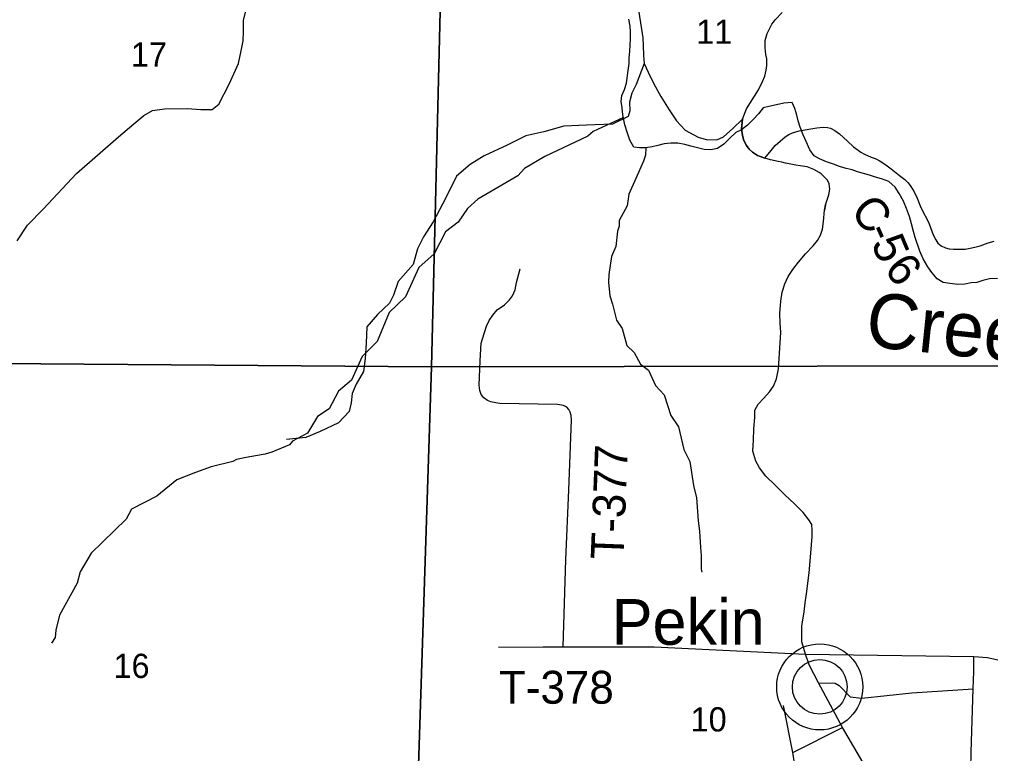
# Model space of a CAD drawing. Extents: x 2.1 to 8.9, y 14.1 to 20.9.
# Drawn here: x 3.78 to 5.459, y 16.441 to 17.71 of the extents above; entities that cross this region are included whole.
import ezdxf

# ---------------------------------------------------------------- set-up
doc = ezdxf.new("R2010")
doc.units = 0
for name, color, linetype in [('GM_X_City_Street', 7, 'Continuous'), ('GM_X_County_Road_Text', 7, 'Continuous'), ('GM_X_Interchange_Ramps', 7, 'Continuous'), ('GM_X_Major_River', 7, 'Continuous'), ('GM_X_Minor_River', 7, 'Continuous'), ('GM_X_Minor_River_Text', 7, 'Continuous'), ('GM_X_Rail_Line_Text', 7, 'Continuous'), ('GM_X_State_Route', 7, 'Continuous'), ('GM_X_State_Shield', 7, 'Continuous'), ('GM_X_Township_Text', 7, 'Continuous'), ('PV_P_Text', 7, 'Continuous'), ('SH_Data', 7, 'Continuous'), ('TX_P_Misc', 7, 'Continuous')]:
    doc.layers.add(name, color=color, linetype=linetype)

msp = doc.modelspace()

# ---------------------------------------------------------------- linework, layer by layer
at = {"layer": 'GM_X_City_Street'}
for p, q in [((4.1678, 17.7086), (4.176, 17.7412)), ((4.1675, 17.6895), (4.1678, 17.7086)), ((4.1668, 17.673), (4.1675, 17.6895)), ((4.1636, 17.6561), (4.1668, 17.673)), ((4.159, 17.6343), (4.1636, 17.6561)), ((4.1427, 17.5984), (4.159, 17.6343)), ((4.8603, 17.634), (4.8464, 17.598)), ((4.1252, 17.5639), (4.1427, 17.5984)), ((4.8464, 17.598), (4.8387, 17.5827)), ((4.8387, 17.5827), (4.8348, 17.5674)), ((4.1137, 17.5544), (4.1252, 17.5639)), ((4.8348, 17.5674), (4.8351, 17.5522)), ((3.9781, 17.5298), (3.9953, 17.544)), ((3.9953, 17.544), (4.0106, 17.5526)), ((4.0106, 17.5526), (4.0313, 17.5558)), ((4.0313, 17.5558), (4.0706, 17.5564)), ((4.0706, 17.5564), (4.0942, 17.5547)), ((4.0942, 17.5547), (4.099, 17.5547)), ((4.099, 17.5547), (4.1137, 17.5544)), ((4.8323, 17.5423), (4.8056, 17.5293)), ((4.8351, 17.5522), (4.8323, 17.5423)), ((3.9517, 17.5074), (3.9781, 17.5298)), ((4.7213, 17.5255), (4.6867, 17.5158)), ((4.7603, 17.5273), (4.7213, 17.5255)), ((4.8056, 17.5293), (4.7603, 17.5273)), ((3.8789, 17.4441), (3.9517, 17.5074)), ((4.6558, 17.5088), (4.6236, 17.493)), ((4.6867, 17.5158), (4.6558, 17.5088)), ((4.6236, 17.493), (4.5834, 17.4744)), ((4.5834, 17.4744), (4.5595, 17.4596)), ((4.5595, 17.4596), (4.536, 17.4394)), ((3.8222, 17.383), (3.8789, 17.4441)), ((4.536, 17.4394), (4.5166, 17.4007)), ((4.5166, 17.4007), (4.4957, 17.3604)), ((3.7944, 17.3548), (3.8222, 17.383)), ((4.4957, 17.3604), (4.4788, 17.3347)), ((3.7763, 17.3273), (3.7944, 17.3548)), ((4.4788, 17.3347), (4.4682, 17.3136)), ((4.4682, 17.3136), (4.4611, 17.2865)), ((4.4611, 17.2865), (4.4351, 17.2575)), ((4.6397, 17.2557), (4.6457, 17.279)), ((4.4351, 17.2575), (4.4268, 17.2338)), ((4.6373, 17.243), (4.6397, 17.2557)), ((4.6324, 17.2326), (4.6373, 17.243)), ((4.4268, 17.2338), (4.4199, 17.2197)), ((4.6186, 17.217), (4.6272, 17.2254)), ((4.6272, 17.2254), (4.6324, 17.2326)), ((4.4199, 17.2197), (4.3994, 17.2003)), ((4.5987, 17.1993), (4.6062, 17.2083)), ((4.6062, 17.2083), (4.6186, 17.217)), ((4.3994, 17.2003), (4.3809, 17.1791)), ((4.5877, 17.1799), (4.5923, 17.1899)), ((4.5923, 17.1899), (4.5987, 17.1993)), ((4.3809, 17.1791), (4.3795, 17.1506)), ((4.5805, 17.1584), (4.5877, 17.1799)), ((4.5787, 17.1504), (4.5805, 17.1584)), ((4.3795, 17.1506), (4.3777, 17.1239)), ((4.5765, 17.1201), (4.5787, 17.1504)), ((4.3777, 17.1239), (4.375, 17.1015)), ((4.5751, 17.0782), (4.5765, 17.1201)), ((4.375, 17.1015), (4.3625, 17.08)), ((4.3625, 17.08), (4.3556, 17.0639)), ((4.5761, 17.0691), (4.5751, 17.0782)), ((4.3556, 17.0639), (4.354, 17.0475)), ((4.5785, 17.0619), (4.5761, 17.0691)), ((4.5829, 17.0561), (4.5785, 17.0619)), ((4.5893, 17.0513), (4.5829, 17.0561)), ((4.354, 17.0475), (4.3501, 17.0323)), ((4.5949, 17.0491), (4.5893, 17.0513)), ((4.6038, 17.0473), (4.5949, 17.0491)), ((4.6106, 17.0463), (4.6038, 17.0473)), ((4.7105, 17.0445), (4.6106, 17.0463)), ((4.7205, 17.0429), (4.7105, 17.0445)), ((4.7263, 17.0399), (4.7205, 17.0429)), ((4.7301, 17.036), (4.7263, 17.0399)), ((4.3501, 17.0323), (4.3319, 17.0129)), ((4.7325, 17.0316), (4.7301, 17.036)), ((4.7339, 17.0258), (4.7325, 17.0316)), ((4.7345, 17.0182), (4.7339, 17.0258)), ((4.3319, 17.0129), (4.3, 16.9979)), ((4.7299, 16.8968), (4.7345, 17.0182)), ((4.2752, 16.9876), (4.242, 16.984)), ((4.3, 16.9979), (4.2752, 16.9876)), ((4.7249, 16.7769), (4.7299, 16.8968)), ((4.7199, 16.6259), (4.7249, 16.7769)), ((4.6084, 16.625), (4.6858, 16.6257)), ((4.6858, 16.6257), (4.7018, 16.6259)), ((4.7018, 16.6259), (4.7199, 16.6259)), ((4.7199, 16.6259), (4.7998, 16.6259)), ((4.7998, 16.6259), (4.8777, 16.626)), ((4.8777, 16.626), (5.1389, 16.613)), ((5.1389, 16.613), (5.4299, 16.6088)), ((5.4299, 16.6088), (5.4537, 16.6073)), ((5.4299, 16.5831), (5.4299, 16.6088)), ((5.4537, 16.6073), (5.4922, 16.5985)), ((5.429, 16.5529), (5.4299, 16.5831)), ((5.1612, 16.5634), (5.1902, 16.5627)), ((5.1902, 16.5627), (5.1974, 16.5586)), ((5.1974, 16.5586), (5.216, 16.5394)), ((5.3225, 16.5464), (5.429, 16.5529)), ((5.4251, 16.4434), (5.429, 16.5529)), ((5.216, 16.5394), (5.2363, 16.537)), ((5.2363, 16.537), (5.3225, 16.5464)), ((5.1173, 16.4432), (5.1012, 16.5243)), ((5.1173, 16.4432), (5.2031, 16.4864)), ((5.1293, 16.3639), (5.1173, 16.4432)), ((5.4248, 16.415), (5.4251, 16.4434))]:
    msp.add_line(p, q, dxfattribs=at)
at = {"layer": 'GM_X_Interchange_Ramps'}
for p, q in [((4.5166, 18.1148), (4.4928, 17.1099)), ((4.4928, 17.1099), (4.5166, 18.1148)), ((4.4928, 17.1099), (3.4934, 17.1171)), ((3.4934, 17.1171), (4.4928, 17.1099)), ((4.4928, 17.1099), (4.4591, 16.088)), ((4.4591, 16.088), (4.4928, 17.1099)), ((5.492, 17.1117), (4.4928, 17.1099)), ((4.4928, 17.1099), (5.492, 17.1117))]:
    msp.add_line(p, q, dxfattribs=at)
at = {"layer": 'GM_X_Rail_Line_Text'}
for p, q in [((5.0839, 17.7058), (5.0867, 17.7098)), ((5.0867, 17.7098), (5.0989, 17.7224)), ((5.0728, 17.686), (5.0766, 17.6941)), ((5.0766, 17.6941), (5.081, 17.7018)), ((5.081, 17.7018), (5.0839, 17.7058)), ((5.0695, 17.6737), (5.0728, 17.686)), ((5.0695, 17.6611), (5.0695, 17.6737)), ((5.0705, 17.6494), (5.0695, 17.6611)), ((5.0719, 17.6422), (5.0705, 17.6494)), ((5.0722, 17.6308), (5.0719, 17.6422)), ((5.0713, 17.6223), (5.0722, 17.6308)), ((5.0649, 17.6028), (5.0685, 17.6121)), ((5.0685, 17.6121), (5.0713, 17.6223)), ((5.0577, 17.5884), (5.0649, 17.6028)), ((5.0373, 17.556), (5.0507, 17.5778)), ((5.0507, 17.5778), (5.0577, 17.5884)), ((5.0299, 17.5378), (5.0373, 17.556)), ((5.0283, 17.5209), (5.0299, 17.5378)), ((5.0301, 17.5094), (5.0283, 17.5209)), ((5.0322, 17.5009), (5.0301, 17.5094)), ((5.0369, 17.4925), (5.0322, 17.5009)), ((5.0418, 17.4862), (5.0369, 17.4925)), ((5.0473, 17.4808), (5.0418, 17.4862)), ((5.0559, 17.4751), (5.0473, 17.4808)), ((5.0686, 17.4706), (5.0559, 17.4751)), ((5.0783, 17.4676), (5.0686, 17.4706)), ((5.0918, 17.4648), (5.0783, 17.4676)), ((5.0983, 17.4634), (5.0918, 17.4648)), ((5.1047, 17.4616), (5.0983, 17.4634)), ((5.1076, 17.4611), (5.1047, 17.4616)), ((5.1222, 17.4586), (5.1076, 17.4611)), ((5.1296, 17.4574), (5.1222, 17.4586)), ((5.1418, 17.4552), (5.1296, 17.4574)), ((5.1535, 17.4507), (5.1418, 17.4552)), ((5.1624, 17.4455), (5.1535, 17.4507)), ((5.1662, 17.4432), (5.1624, 17.4455)), ((5.1702, 17.4396), (5.1662, 17.4432)), ((5.1769, 17.4324), (5.1702, 17.4396)), ((5.1799, 17.4258), (5.1769, 17.4324)), ((5.1812, 17.4169), (5.1799, 17.4258)), ((5.1737, 17.3895), (5.1794, 17.407)), ((5.1794, 17.407), (5.1812, 17.4169)), ((5.1721, 17.3806), (5.1737, 17.3895)), ((5.1702, 17.3611), (5.1721, 17.3806)), ((5.1682, 17.3477), (5.1702, 17.3611)), ((5.1649, 17.3375), (5.1682, 17.3477)), ((5.1521, 17.3188), (5.1597, 17.3283)), ((5.1597, 17.3283), (5.1649, 17.3375)), ((5.1389, 17.3052), (5.1521, 17.3188)), ((5.117, 17.2778), (5.1267, 17.2904)), ((5.1267, 17.2904), (5.1389, 17.3052)), ((5.1093, 17.2659), (5.117, 17.2778)), ((5.103, 17.2531), (5.1093, 17.2659)), ((5.0962, 17.2232), (5.0984, 17.239)), ((5.0984, 17.239), (5.103, 17.2531)), ((5.0945, 17.2019), (5.0962, 17.2232)), ((5.095, 17.1857), (5.0945, 17.2019)), ((5.0962, 17.1691), (5.095, 17.1857)), ((5.0954, 17.1513), (5.0962, 17.1691)), ((5.0923, 17.106), (5.0954, 17.1513)), ((5.0887, 17.0888), (5.0923, 17.106)), ((5.0836, 17.0762), (5.0887, 17.0888)), ((5.0768, 17.0667), (5.0836, 17.0762)), ((5.0569, 17.0452), (5.0671, 17.0558)), ((5.0671, 17.0558), (5.0768, 17.0667)), ((5.0516, 17.0347), (5.0569, 17.0452)), ((5.0498, 17.0028), (5.0514, 17.0224)), ((5.0514, 17.0224), (5.0516, 17.0347)), ((5.049, 16.9831), (5.0498, 17.0028)), ((5.0479, 16.9641), (5.049, 16.9831)), ((5.0534, 16.9467), (5.0479, 16.9641)), ((5.0595, 16.9353), (5.0534, 16.9467)), ((5.0704, 16.9205), (5.0595, 16.9353)), ((5.0863, 16.9054), (5.0704, 16.9205)), ((5.1025, 16.8889), (5.0863, 16.9054)), ((5.1206, 16.8725), (5.1025, 16.8889)), ((5.135, 16.8581), (5.1206, 16.8725)), ((5.145, 16.8452), (5.135, 16.8581)), ((5.1498, 16.8371), (5.145, 16.8452)), ((5.1507, 16.8268), (5.1498, 16.8371)), ((5.1507, 16.8166), (5.1507, 16.8268)), ((5.1483, 16.7874), (5.1507, 16.8166)), ((5.1452, 16.7535), (5.1483, 16.7874)), ((5.1406, 16.7175), (5.1452, 16.7535)), ((5.1367, 16.6861), (5.1386, 16.7018)), ((5.1386, 16.7018), (5.1406, 16.7175)), ((5.1324, 16.6612), (5.1367, 16.6861)), ((5.1326, 16.6346), (5.1324, 16.6612)), ((5.1389, 16.613), (5.1326, 16.6346)), ((5.1454, 16.5944), (5.1389, 16.613)), ((5.1612, 16.5634), (5.1454, 16.5944)), ((5.2031, 16.4864), (5.1612, 16.5634)), ((5.2634, 16.3835), (5.2031, 16.4864))]:
    msp.add_line(p, q, dxfattribs=at)
at = {"layer": 'GM_X_State_Route'}
for radius in [0.0744, 0.0472]:
    msp.add_circle((5.1636, 16.5565), radius, dxfattribs=at)
at = {"layer": 'GM_X_State_Shield'}
for p, q in [((4.8512, 17.7226), (4.8578, 17.6782)), ((4.8578, 17.6782), (4.8582, 17.665)), ((4.8582, 17.665), (4.8589, 17.6477)), ((4.8589, 17.6477), (4.8603, 17.634)), ((4.8603, 17.634), (4.8668, 17.619)), ((4.8668, 17.619), (4.8766, 17.599)), ((4.8766, 17.599), (4.8891, 17.577)), ((4.8891, 17.577), (4.9036, 17.5542)), ((4.9036, 17.5542), (4.9163, 17.535)), ((4.9163, 17.535), (4.9313, 17.5189)), ((5.0135, 17.5215), (5.0299, 17.5378)), ((5.0299, 17.5378), (5.0283, 17.5209)), ((5.1587, 17.5231), (5.1696, 17.5238)), ((5.1696, 17.5238), (5.177, 17.5233)), ((4.9313, 17.5189), (4.9536, 17.5067)), ((4.9536, 17.5067), (4.9673, 17.503)), ((4.9857, 17.5023), (4.9971, 17.5075)), ((4.9971, 17.5075), (5.0135, 17.5215)), ((5.0283, 17.5209), (5.0301, 17.5094)), ((5.0301, 17.5094), (5.0322, 17.5009)), ((5.0865, 17.4923), (5.1041, 17.5075)), ((5.1041, 17.5075), (5.1103, 17.5112)), ((5.1103, 17.5112), (5.1167, 17.5141)), ((5.1167, 17.5141), (5.1225, 17.5161)), ((5.1225, 17.5161), (5.1282, 17.5178)), ((5.1282, 17.5178), (5.1587, 17.5231)), ((5.177, 17.5233), (5.182, 17.5223)), ((5.182, 17.5223), (5.1897, 17.5185)), ((5.1897, 17.5185), (5.1979, 17.5124)), ((5.1979, 17.5124), (5.2118, 17.4998)), ((4.9673, 17.503), (4.9857, 17.5023)), ((5.0322, 17.5009), (5.0369, 17.4925)), ((5.0369, 17.4925), (5.0418, 17.4862)), ((5.0794, 17.4839), (5.0865, 17.4923)), ((5.2118, 17.4998), (5.2222, 17.4903)), ((5.2222, 17.4903), (5.2299, 17.4843)), ((5.0418, 17.4862), (5.0473, 17.4808)), ((5.0473, 17.4808), (5.0559, 17.4751)), ((5.0559, 17.4751), (5.0686, 17.4706)), ((5.0686, 17.4706), (5.0794, 17.4839)), ((5.2299, 17.4843), (5.2346, 17.4811)), ((5.2346, 17.4811), (5.2411, 17.4774)), ((5.2411, 17.4774), (5.2527, 17.4719)), ((5.2527, 17.4719), (5.2592, 17.4697)), ((5.2592, 17.4697), (5.2663, 17.4665)), ((5.2663, 17.4665), (5.2777, 17.4591)), ((5.2777, 17.4591), (5.2871, 17.4519)), ((5.2871, 17.4519), (5.3015, 17.4404)), ((5.3015, 17.4404), (5.3105, 17.4337)), ((5.3105, 17.4337), (5.3164, 17.4276)), ((5.3164, 17.4276), (5.3209, 17.4216)), ((5.3209, 17.4216), (5.3266, 17.4121)), ((5.3266, 17.4121), (5.3318, 17.4013)), ((5.3318, 17.4013), (5.3373, 17.3878)), ((5.3373, 17.3878), (5.3428, 17.376)), ((5.3428, 17.376), (5.3484, 17.3665)), ((5.3484, 17.3665), (5.3526, 17.3568)), ((5.3526, 17.3568), (5.3594, 17.3382)), ((5.3594, 17.3382), (5.3641, 17.3291)), ((5.3641, 17.3291), (5.3676, 17.3233)), ((5.3676, 17.3233), (5.3735, 17.3189)), ((5.4407, 17.3191), (5.4548, 17.3238)), ((5.4548, 17.3238), (5.465, 17.3268)), ((5.3735, 17.3189), (5.3809, 17.3154)), ((5.3809, 17.3154), (5.3874, 17.3137)), ((5.3874, 17.3137), (5.3949, 17.313)), ((5.3949, 17.313), (5.406, 17.3129)), ((5.406, 17.3129), (5.4152, 17.3134)), ((5.4152, 17.3134), (5.4234, 17.3149)), ((5.4234, 17.3149), (5.4315, 17.3166)), ((5.4315, 17.3166), (5.4407, 17.3191))]:
    msp.add_line(p, q, dxfattribs=at)
at = {"layer": 'GM_X_Township_Text'}
msp.add_line((5.1636, 16.5565), (5.1636, 16.5565), dxfattribs=at)
at = {"layer": 'SH_Data'}
msp.add_line((5.1737, 17.3895), (5.1721, 17.3806), dxfattribs=at)
msp.add_lwpolyline([(5.1737, 17.3895), (5.1794, 17.407), (5.1794, 17.407), (5.1812, 17.4169), (5.1799, 17.4258), (5.1769, 17.4324), (5.1702, 17.4396), (5.1662, 17.4432), (5.1624, 17.4455), (5.1535, 17.4507), (5.1418, 17.4552), (5.1296, 17.4574), (5.1222, 17.4586), (5.1076, 17.4611), (5.1047, 17.4616), (5.0983, 17.4634), (5.0918, 17.4648), (5.0783, 17.4676)], dxfattribs=at)
at = {"layer": 'TX_P_Misc'}
for p, q in [((4.8359, 17.6988), (4.8336, 17.7106)), ((4.8365, 17.689), (4.8359, 17.6988)), ((4.8357, 17.6661), (4.8366, 17.6756)), ((4.8366, 17.6756), (4.8365, 17.689)), ((4.8353, 17.6547), (4.8357, 17.6661)), ((4.834, 17.6341), (4.8345, 17.644)), ((4.8345, 17.644), (4.8353, 17.6547)), ((4.8325, 17.6222), (4.834, 17.6341)), ((4.8298, 17.6), (4.8325, 17.6222)), ((4.8263, 17.5889), (4.8298, 17.6)), ((4.8205, 17.5685), (4.8213, 17.5788)), ((4.8213, 17.5788), (4.8263, 17.5889)), ((4.8223, 17.5572), (4.8205, 17.5685)), ((4.8235, 17.5454), (4.8223, 17.5572)), ((5.0657, 17.5572), (5.0576, 17.547)), ((5.0755, 17.5598), (5.0657, 17.5572)), ((5.0891, 17.5629), (5.0755, 17.5598)), ((5.1015, 17.5656), (5.0891, 17.5629)), ((5.116, 17.5668), (5.1015, 17.5656)), ((5.1205, 17.5563), (5.116, 17.5668)), ((4.8244, 17.5409), (4.7719, 17.5168)), ((4.827, 17.528), (4.8235, 17.5454)), ((5.0576, 17.547), (5.0484, 17.5372)), ((5.1239, 17.5446), (5.1205, 17.5563)), ((5.1261, 17.5347), (5.1239, 17.5446)), ((4.8308, 17.5156), (4.827, 17.528)), ((5.0388, 17.5274), (5.0284, 17.5195)), ((5.0484, 17.5372), (5.0388, 17.5274)), ((5.1298, 17.5242), (5.1261, 17.5347)), ((5.1348, 17.511), (5.1298, 17.5242)), ((4.7629, 17.5087), (4.6883, 17.4736)), ((4.7719, 17.5168), (4.7629, 17.5087)), ((4.8355, 17.5016), (4.8308, 17.5156)), ((5.0187, 17.515), (5.0084, 17.5048)), ((5.0284, 17.5195), (5.0187, 17.515)), ((5.1401, 17.499), (5.1348, 17.511)), ((4.8423, 17.4893), (4.8355, 17.5016)), ((4.8742, 17.4903), (4.8632, 17.4884)), ((4.884, 17.4921), (4.8742, 17.4903)), ((4.895, 17.4951), (4.884, 17.4921)), ((4.9063, 17.4962), (4.895, 17.4951)), ((4.9185, 17.4962), (4.9063, 17.4962)), ((4.9304, 17.4939), (4.9185, 17.4962)), ((4.9407, 17.4912), (4.9304, 17.4939)), ((4.9526, 17.4885), (4.9407, 17.4912)), ((4.9976, 17.4949), (4.9868, 17.4873)), ((5.0084, 17.5048), (4.9976, 17.4949)), ((5.1462, 17.4851), (5.1401, 17.499)), ((4.6883, 17.4736), (4.6535, 17.4524)), ((4.8522, 17.4884), (4.8423, 17.4893)), ((4.8632, 17.4884), (4.8522, 17.4884)), ((4.8622, 17.4757), (4.8589, 17.4654)), ((4.8633, 17.4884), (4.8622, 17.4757)), ((4.9637, 17.4855), (4.9526, 17.4885)), ((4.9755, 17.4847), (4.9637, 17.4855)), ((4.9868, 17.4873), (4.9755, 17.4847)), ((5.1538, 17.4747), (5.1462, 17.4851)), ((5.1634, 17.4693), (5.1538, 17.4747)), ((4.8589, 17.4654), (4.8458, 17.4355)), ((5.1754, 17.4639), (5.1634, 17.4693)), ((5.1873, 17.4601), (5.1754, 17.4639)), ((5.198, 17.4563), (5.1873, 17.4601)), ((4.642, 17.4397), (4.5728, 17.3993)), ((4.6535, 17.4524), (4.642, 17.4397)), ((5.2092, 17.4528), (5.198, 17.4563)), ((5.2195, 17.4501), (5.2092, 17.4528)), ((5.2291, 17.447), (5.2195, 17.4501)), ((5.2391, 17.4438), (5.2291, 17.447)), ((5.2498, 17.4408), (5.2391, 17.4438)), ((5.2598, 17.4376), (5.2498, 17.4408)), ((4.8458, 17.4355), (4.8338, 17.4082)), ((5.2702, 17.4349), (5.2598, 17.4376)), ((5.2829, 17.43), (5.2702, 17.4349)), ((5.2942, 17.4201), (5.2829, 17.43)), ((4.8338, 17.4082), (4.8308, 17.388)), ((5.301, 17.4092), (5.2942, 17.4201)), ((5.3082, 17.3961), (5.301, 17.4092)), ((4.5728, 17.3993), (4.5549, 17.3834)), ((5.3136, 17.3833), (5.3082, 17.3961)), ((4.5549, 17.3834), (4.5387, 17.36)), ((4.8308, 17.388), (4.8172, 17.3627)), ((5.3189, 17.3698), (5.3136, 17.3833)), ((4.5387, 17.36), (4.517, 17.3432)), ((4.8172, 17.3627), (4.817, 17.3528)), ((5.3224, 17.357), (5.3189, 17.3698)), ((5.3258, 17.3434), (5.3224, 17.357)), ((4.517, 17.3432), (4.4973, 17.3048)), ((4.8138, 17.344), (4.8112, 17.318)), ((4.817, 17.3528), (4.8138, 17.344)), ((5.3288, 17.3332), (5.3258, 17.3434)), ((5.3364, 17.3098), (5.3288, 17.3332)), ((4.8112, 17.318), (4.8036, 17.3004)), ((5.3425, 17.2967), (5.3364, 17.3098)), ((4.4973, 17.3048), (4.4708, 17.2816)), ((4.8036, 17.3004), (4.7992, 17.2691)), ((5.3505, 17.2828), (5.3425, 17.2967)), ((4.4708, 17.2816), (4.4479, 17.2306)), ((5.3573, 17.2727), (5.3505, 17.2828)), ((5.3663, 17.2616), (5.3573, 17.2727)), ((4.7992, 17.2691), (4.7983, 17.2562)), ((4.7983, 17.2562), (4.8006, 17.2322)), ((5.3768, 17.2554), (5.3663, 17.2616)), ((5.3882, 17.2539), (5.3768, 17.2554)), ((5.4251, 17.2551), (5.4141, 17.2528)), ((5.4353, 17.2554), (5.4251, 17.2551)), ((5.4455, 17.2587), (5.4353, 17.2554)), ((5.4572, 17.2618), (5.4455, 17.2587)), ((5.4709, 17.2626), (5.4572, 17.2618)), ((5.402, 17.2521), (5.3882, 17.2539)), ((5.4141, 17.2528), (5.402, 17.2521)), ((4.4479, 17.2306), (4.4196, 17.2038)), ((4.8006, 17.2322), (4.8057, 17.2182)), ((4.8057, 17.2182), (4.8126, 17.1905)), ((4.4196, 17.2038), (4.3986, 17.1533)), ((4.8126, 17.1905), (4.8219, 17.1758)), ((4.8219, 17.1758), (4.8304, 17.1467)), ((4.3986, 17.1533), (4.3726, 17.1277)), ((4.8304, 17.1467), (4.8431, 17.1347)), ((4.3726, 17.1277), (4.3544, 17.0867)), ((4.8431, 17.1347), (4.854, 17.1143)), ((4.854, 17.1143), (4.8678, 17.1039)), ((4.8678, 17.1039), (4.8799, 17.0775)), ((4.3544, 17.0867), (4.3316, 17.0677)), ((4.8799, 17.0775), (4.8946, 17.0613)), ((4.3316, 17.0677), (4.3155, 17.0373)), ((4.8946, 17.0613), (4.9062, 17.0257)), ((4.3155, 17.0373), (4.2953, 17.0237)), ((4.2953, 17.0237), (4.2781, 16.9952)), ((4.9062, 17.0257), (4.9197, 17.0062)), ((4.9197, 17.0062), (4.9287, 16.9667)), ((4.2781, 16.9952), (4.2526, 16.9815)), ((4.2474, 16.9749), (4.2166, 16.9623)), ((4.2526, 16.9815), (4.2474, 16.9749)), ((4.1722, 16.9532), (4.1556, 16.9495)), ((4.2016, 16.9582), (4.1722, 16.9532)), ((4.2053, 16.959), (4.2016, 16.9582)), ((4.2166, 16.9623), (4.2053, 16.959)), ((4.9287, 16.9667), (4.9389, 16.946)), ((4.1116, 16.9366), (4.0849, 16.927)), ((4.1492, 16.9463), (4.1116, 16.9366)), ((4.1556, 16.9495), (4.1492, 16.9463)), ((4.9389, 16.946), (4.9456, 16.9046)), ((4.0849, 16.927), (4.0523, 16.9143)), ((4.0523, 16.9143), (4.0176, 16.8863)), ((4.9456, 16.9046), (4.9505, 16.8833)), ((4.0176, 16.8863), (3.9738, 16.8635)), ((4.9505, 16.8833), (4.9535, 16.8434)), ((3.9738, 16.8635), (3.9646, 16.8466)), ((3.9646, 16.8466), (3.9044, 16.7878)), ((4.9535, 16.8434), (4.9557, 16.8256)), ((4.9557, 16.8256), (4.9573, 16.7974)), ((3.9044, 16.7878), (3.8853, 16.7555)), ((4.9573, 16.7974), (4.9587, 16.7837)), ((4.9587, 16.7837), (4.9587, 16.7598)), ((3.8853, 16.7555), (3.8799, 16.7356)), ((4.9587, 16.7598), (4.9599, 16.7548)), ((3.8799, 16.7356), (3.8499, 16.6807)), ((3.8499, 16.6807), (3.8435, 16.6547)), ((3.8435, 16.6547), (3.8419, 16.6418)), ((3.8419, 16.6418), (3.8356, 16.6318))]:
    msp.add_line(p, q, dxfattribs=at)

# ---------------------------------------------------------------- texts
at = {"layer": 'GM_X_County_Road_Text'}
for s, p in [('11', (4.9501, 17.6681)), ('17', (3.973, 17.6287)), ('16', (3.943, 16.5719)), ('10', (4.9405, 16.4794))]:
    msp.add_text(s, height=0.04186, rotation=0, dxfattribs=at).set_placement(p)
at = {"layer": 'GM_X_Major_River'}
msp.add_text('Pekin', height=0.07898, rotation=0, dxfattribs=at).set_placement((4.8042, 16.6293))
at = {"layer": 'GM_X_Minor_River'}
for s, rotation, p in [('C', 310.9535, (5.2143, 17.3766)), ('5', 292.8925, (5.2519, 17.324)), ('-', 293.9704, (5.2425, 17.3451)), ('6', 307.4157, (5.2734, 17.2782))]:
    msp.add_text(s, height=0.0568, rotation=rotation, dxfattribs=at).set_placement(p)
at = {"layer": 'GM_X_Minor_River_Text'}
for s, rotation, p in [('T-377', 87.755, (4.8244, 16.7758)), ('T-378', 0, (4.6092, 16.5274))]:
    msp.add_text(s, height=0.05682, rotation=rotation, dxfattribs=at).set_placement(p)
at = {"layer": 'PV_P_Text'}
msp.add_text('Creek', height=0.0947, rotation=354.0791, dxfattribs=at).set_placement((5.2404, 17.1456))

doc.saveas('drawing.dxf')
